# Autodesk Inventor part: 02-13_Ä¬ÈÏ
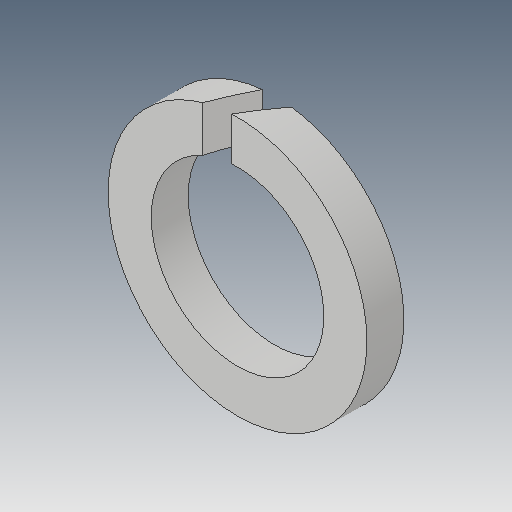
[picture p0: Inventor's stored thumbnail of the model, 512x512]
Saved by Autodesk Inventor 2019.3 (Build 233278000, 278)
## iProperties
Created: 2010-06
Part Number: 02-13_Ä¬ÈÏ
Material: Ogólny
Document SubType Name: Modeling
Designer: CADENGINEERING4
Density: 1 g/cm^3
Appearance: Domyślna
Author: CADENGINEERING4
Revision Number: ÈÎºÎ
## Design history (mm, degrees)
feature "NONE"
node "Bryła1"
